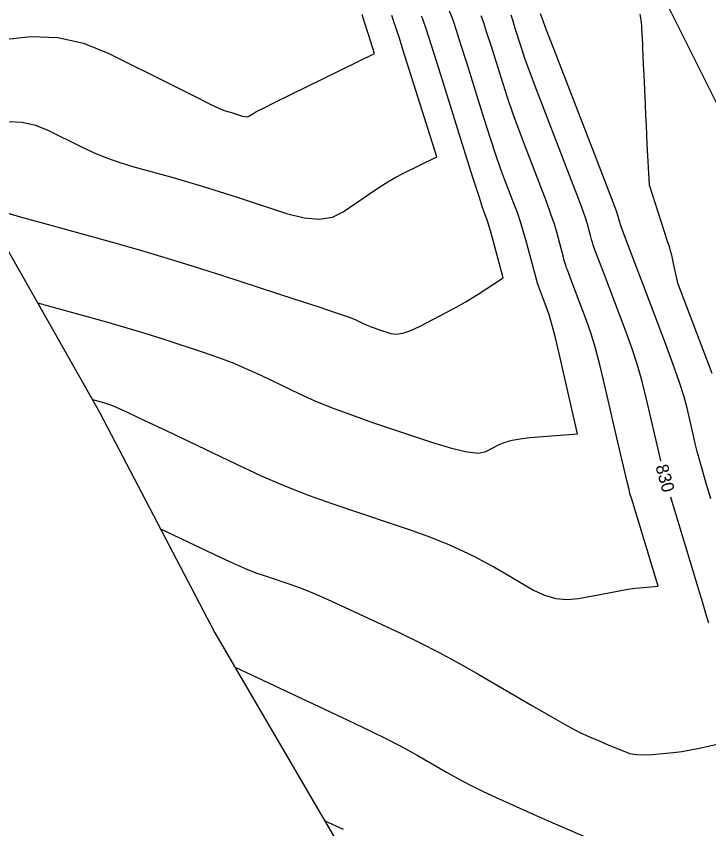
# Model space of a CAD drawing. Extents: x 1715724 to 1716561, y 394063 to 395906.
# Drawn here: x 1716217.6 to 1716294.8, y 394512.3 to 394602.7 of the extents above; entities that cross this region are included whole.
import ezdxf

# ---------------------------------------------------------------- set-up
doc = ezdxf.new("R2010")
doc.units = 0
for name, color, linetype in [('DT_X_Contour_Major', 7, 'Continuous'), ('DT_X_Contour_Minor', 7, 'Continuous'), ('DT_X_TIN_Hull', 7, 'Continuous'), ('GE_P_CL_10', 7, 'Continuous')]:
    doc.layers.add(name, color=color, linetype=linetype)

msp = doc.modelspace()

# ---------------------------------------------------------------- linework, layer by layer
at = {"layer": 'DT_X_Contour_Major'}
for points in [[(1716216.201, 394600.17), (1716219.288, 394600.511), (1716222.262, 394600.37), (1716225.121, 394599.748), (1716227.865, 394598.644), (1716235.033, 394595.059), (1716237.408, 394593.876), (1716239.16, 394593.016), (1716240.287, 394592.479), (1716240.791, 394592.264), (1716241.301, 394592.123), (1716241.499, 394592.067), (1716241.713, 394592.003), (1716241.941, 394591.932), (1716242.184, 394591.854), (1716242.851, 394591.636), (1716243.086, 394591.576), (1716243.292, 394591.56), (1716243.469, 394591.586), (1716243.616, 394591.656), (1716243.969, 394591.9), (1716244.334, 394592.102), (1716245.165, 394592.526), (1716246.463, 394593.171), (1716248.226, 394594.037), (1716257.542, 394598.595), (1716256.873, 394600.722), (1716256.829, 394600.859), (1716256.81, 394600.915), (1716256.796, 394600.952), (1716256.434, 394602.083), (1716256.16, 394602.944)], [(1716289.438, 394553.269), (1716289.281, 394553.93), (1716288.907, 394555.535), (1716287.807, 394560.291), (1716287.358, 394562.086), (1716286.834, 394563.902), (1716286.237, 394565.74), (1716285.566, 394567.6), (1716283.678, 394572.588), (1716283.051, 394574.245), (1716282.282, 394576.276), (1716282.141, 394576.65), (1716281.979, 394577.078), (1716281.91, 394577.277), (1716281.825, 394577.553), (1716281.724, 394577.907), (1716281.607, 394578.339), (1716281.272, 394579.594), (1716281.039, 394580.322), (1716280.593, 394581.566), (1716279.933, 394583.326), (1716279.059, 394585.6), (1716276.445, 394592.354), (1716275.553, 394594.677), (1716274.84, 394596.58), (1716274.304, 394598.063), (1716273.946, 394599.127), (1716273.23, 394601.403), (1716272.976, 394602.198), (1716272.752, 394602.875)], [(1716294.806, 394535.176), (1716294.54, 394536.001), (1716293.998, 394537.83), (1716293.761, 394538.624), (1716293.085, 394540.865), (1716290.624, 394548.968), (1716290.548, 394549.22)], [(1716233.707, 394545.704), (1716240.419, 394542.502), (1716241.813, 394541.856), (1716243.116, 394541.292), (1716244.33, 394540.808), (1716245.454, 394540.407), (1716248.332, 394539.443), (1716249.542, 394539.002), (1716251.016, 394538.402), (1716252.751, 394537.642), (1716254.75, 394536.724), (1716260.43, 394534.062), (1716262.573, 394533.026), (1716264.744, 394531.914), (1716266.943, 394530.727), (1716269.169, 394529.465), (1716275.142, 394525.999), (1716277.152, 394524.839), (1716278.703, 394523.958), (1716279.793, 394523.358), (1716280.424, 394523.038), (1716281.494, 394522.556), (1716281.926, 394522.364), (1716282.42, 394522.15), (1716282.975, 394521.912), (1716283.591, 394521.652), (1716285.317, 394520.927), (1716285.997, 394520.701), (1716286.742, 394520.565), (1716287.552, 394520.52), (1716288.427, 394520.567), (1716290.848, 394520.811), (1716291.772, 394520.922), (1716292.731, 394521.073), (1716293.724, 394521.263), (1716294.75, 394521.492), (1716299.62, 394522.654)]]:
    msp.add_lwpolyline(points, dxfattribs=at)
at = {"layer": 'DT_X_Contour_Minor'}
for points in [[(1716219.991, 394570.848), (1716227.667, 394568.722), (1716229.307, 394568.258), (1716230.938, 394567.777), (1716232.559, 394567.278), (1716234.17, 394566.763), (1716238.455, 394565.366), (1716240.062, 394564.811), (1716241.67, 394564.196), (1716243.279, 394563.519), (1716244.889, 394562.781), (1716249.183, 394560.732), (1716250.9, 394559.957), (1716252.83, 394559.167), (1716254.974, 394558.363), (1716257.33, 394557.546), (1716263.898, 394555.346), (1716266.124, 394554.662), (1716267.874, 394554.257), (1716269.149, 394554.131), (1716269.949, 394554.285), (1716271.448, 394555.07), (1716272.082, 394555.339), (1716272.861, 394555.558), (1716273.783, 394555.725), (1716274.85, 394555.843), (1716280.166, 394556.273), (1716278.102, 394565.194), (1716277.689, 394566.937), (1716277.333, 394568.343), (1716277.034, 394569.412), (1716276.792, 394570.144), (1716275.894, 394572.517), (1716275.711, 394573), (1716275.661, 394573.169), (1716275.548, 394573.581), (1716275.131, 394575.133), (1716274.406, 394577.848), (1716274.119, 394578.865), (1716273.802, 394579.882), (1716273.455, 394580.897), (1716273.077, 394581.912), (1716272.03, 394584.616), (1716271.595, 394585.795), (1716271.074, 394587.305), (1716270.467, 394589.146), (1716269.775, 394591.317), (1716267.815, 394597.548), (1716267.16, 394599.622), (1716266.666, 394601.17), (1716266.332, 394602.192), (1716266.159, 394602.689), (1716265.912, 394603.314)], [(1716295.021, 394549.049), (1716294.541, 394550.645), (1716293.885, 394552.864), (1716293.701, 394553.517), (1716293.498, 394554.293), (1716293.276, 394555.193), (1716293.035, 394556.216), (1716292.366, 394559.109), (1716292.027, 394560.374), (1716291.512, 394561.998), (1716290.821, 394563.983), (1716289.953, 394566.327), (1716287.406, 394573.059), (1716286.56, 394575.294), (1716285.932, 394576.953), (1716285.523, 394578.035), (1716285.113, 394579.116), (1716285.035, 394579.33), (1716284.964, 394579.539), (1716284.901, 394579.743), (1716284.845, 394579.943), (1716284.704, 394580.467), (1716284.499, 394581.051), (1716283.988, 394582.408), (1716283.172, 394584.54), (1716282.05, 394587.445), (1716277.532, 394599.118), (1716276.722, 394601.217), (1716276.222, 394602.522), (1716276.032, 394603.032)], [(1716216.196, 394580.965), (1716218.074, 394580.439), (1716220.679, 394579.716), (1716228.595, 394577.524), (1716231.571, 394576.681), (1716234.562, 394575.797), (1716237.568, 394574.871), (1716240.588, 394573.905), (1716248.663, 394571.271), (1716251.355, 394570.387), (1716253.373, 394569.71), (1716254.719, 394569.24), (1716255.391, 394568.976), (1716256.287, 394568.549), (1716256.645, 394568.387), (1716257.047, 394568.222), (1716257.494, 394568.055), (1716257.986, 394567.884), (1716259.355, 394567.426), (1716259.946, 394567.349), (1716260.691, 394567.463), (1716261.59, 394567.768), (1716262.643, 394568.264), (1716265.656, 394569.842), (1716266.719, 394570.408), (1716267.647, 394570.924), (1716268.441, 394571.39), (1716269.101, 394571.805), (1716271.866, 394573.628), (1716270.758, 394577.779), (1716270.538, 394578.589), (1716270.353, 394579.241), (1716270.202, 394579.733), (1716270.086, 394580.067), (1716269.823, 394580.747), (1716269.616, 394581.354), (1716269.191, 394582.668), (1716268.549, 394584.687), (1716267.689, 394587.412), (1716265.107, 394595.62), (1716264.252, 394598.333), (1716263.622, 394600.318), (1716263.22, 394601.572), (1716263.043, 394602.098), (1716262.873, 394602.527), (1716262.791, 394602.75)], [(1716216.777, 394591.027), (1716218.297, 394590.956), (1716219.759, 394590.637), (1716221.162, 394590.073), (1716224.826, 394588.24), (1716226.226, 394587.584), (1716227.678, 394586.99), (1716229.18, 394586.459), (1716230.735, 394585.99), (1716234.948, 394584.824), (1716236.589, 394584.356), (1716238.351, 394583.83), (1716240.234, 394583.245), (1716242.239, 394582.601), (1716247.747, 394580.805), (1716249.691, 394580.31), (1716251.392, 394580.172), (1716252.849, 394580.392), (1716254.063, 394580.968), (1716256.977, 394582.983), (1716258.032, 394583.692), (1716259.014, 394584.311), (1716259.922, 394584.838), (1716260.756, 394585.273), (1716264.475, 394587.093), (1716260.747, 394598.94), (1716260.315, 394600.307), (1716260.041, 394601.163), (1716259.927, 394601.506), (1716259.834, 394601.739), (1716259.771, 394601.918), (1716259.652, 394602.281), (1716259.476, 394602.826)], [(1716226.115, 394560.093), (1716227.191, 394559.794), (1716227.379, 394559.738), (1716227.566, 394559.681), (1716228.247, 394559.46), (1716228.77, 394559.235), (1716229.967, 394558.681), (1716231.84, 394557.798), (1716234.387, 394556.586), (1716242.08, 394552.915), (1716244.913, 394551.607), (1716247.643, 394550.437), (1716250.269, 394549.404), (1716252.792, 394548.508), (1716259.381, 394546.301), (1716261.641, 394545.531), (1716263.479, 394544.877), (1716264.894, 394544.337), (1716265.888, 394543.913), (1716267.976, 394542.934), (1716268.814, 394542.524), (1716269.762, 394542.028), (1716270.821, 394541.447), (1716271.991, 394540.779), (1716275.257, 394538.883), (1716276.488, 394538.291), (1716277.731, 394537.937), (1716278.986, 394537.82), (1716280.253, 394537.942), (1716283.647, 394538.582), (1716284.815, 394538.797), (1716285.777, 394538.961), (1716286.53, 394539.073), (1716287.076, 394539.134), (1716289.139, 394539.299), (1716286.677, 394547.399), (1716286.195, 394548.988), (1716286.004, 394549.631), (1716285.898, 394550.055), (1716285.659, 394551.067), (1716285.286, 394552.667), (1716284.779, 394554.855), (1716283.248, 394561.473), (1716282.688, 394563.797), (1716282.157, 394565.805), (1716281.654, 394567.497), (1716281.179, 394568.872), (1716279.95, 394572.118), (1716279.542, 394573.196), (1716279.24, 394573.996), (1716279.042, 394574.517), (1716278.95, 394574.761), (1716278.845, 394575.039), (1716278.786, 394575.223), (1716278.686, 394575.567), (1716278.547, 394576.072), (1716278.369, 394576.736), (1716277.839, 394578.721), (1716277.579, 394579.594), (1716277.197, 394580.724), (1716276.694, 394582.111), (1716276.068, 394583.756), (1716274.237, 394588.485), (1716273.574, 394590.236), (1716272.957, 394591.943), (1716272.386, 394593.604), (1716271.861, 394595.222), (1716270.522, 394599.476), (1716270.068, 394600.91), (1716269.709, 394602.022), (1716269.444, 394602.813)], [(1716287.087, 394602.971), (1716287.202, 394602.299), (1716287.246, 394602.043), (1716287.267, 394601.918), (1716287.277, 394601.818), (1716287.29, 394601.614), (1716287.307, 394601.304), (1716287.328, 394600.888), (1716287.387, 394599.641), (1716287.414, 394599.078), (1716287.448, 394598.322), (1716287.49, 394597.375), (1716287.54, 394596.236), (1716287.684, 394592.942), (1716287.738, 394591.74), (1716287.791, 394590.603), (1716287.844, 394589.532), (1716287.896, 394588.525), (1716288.136, 394583.983), (1716289.811, 394578.805), (1716290.127, 394577.826), (1716290.357, 394577.108), (1716290.501, 394576.653), (1716290.558, 394576.458), (1716290.595, 394576.289), (1716290.62, 394576.176), (1716290.668, 394575.962), (1716290.737, 394575.648), (1716290.829, 394575.233), (1716291.309, 394573.065), (1716295.115, 394563.009)], [(1716242.004, 394530.288), (1716254.487, 394524.437), (1716256.981, 394523.251), (1716259.111, 394522.201), (1716260.879, 394521.287), (1716262.284, 394520.509), (1716265.546, 394518.616), (1716266.81, 394517.908), (1716268.155, 394517.203), (1716269.582, 394516.502), (1716271.089, 394515.803), (1716275.218, 394513.946), (1716276.885, 394513.205), (1716278.79, 394512.376), (1716280.931, 394511.46)], [(1716254.082, 394512.218), (1716251.972, 394513.206)]]:
    msp.add_lwpolyline(points, dxfattribs=at)
at = {"layer": 'DT_X_TIN_Hull'}
msp.add_lwpolyline([(1716124.575, 394620.656), (1716148.932, 394620.106), (1716178.473, 394618.573), (1716198.368, 394601.547), (1716214.149, 394581.106), (1716226.914, 394558.689), (1716239.765, 394534.125), (1716253.999, 394509.733), (1716267.482, 394486.319), (1716281.648, 394460.466), (1716295.056, 394433.007), (1716310.248, 394404.289), (1716324.4, 394380.065), (1716338.753, 394353.428), (1716352.69, 394329.698), (1716364.178, 394305.34), (1716366.885, 394280.883)], dxfattribs=at)
at = {"layer": 'GE_P_CL_10'}
msp.add_line((1716447.809, 394289.082), (1716249.46, 394685.42), dxfattribs=at)

# ---------------------------------------------------------------- texts
at = {"layer": 'DT_X_Contour_Major'}
msp.add_text('830', height=1.4, rotation=285.32959, dxfattribs=at).set_placement((1716288.834, 394552.653))

doc.saveas('drawing.dxf')
